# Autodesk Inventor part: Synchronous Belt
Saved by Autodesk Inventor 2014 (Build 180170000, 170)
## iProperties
Created: 2013-12
Part Number: Synchronous Belt
Material: Rubber
Document SubType Name: Modeling
Designer: Bram
Density: 1 g/cm^3
Appearance: Rubber - Black - Version 1.1
CustomPartVersion: 1
Author: Bram
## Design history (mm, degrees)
sketch "Sketch Path"
  geometry: L1 (7.016, -9.44)-(-22.347, -31.263); L2 (-32.146, -26.704)-(-56.472, 373.578); L3 (-34.584, 375.594)-(11.673, 1.443); A1 r 6.145 centre (-26.012, -26.332) between (-32.146, -26.704) and (-22.347, -31.263); A2 r 10.996 centre (-45.496, 374.245) between (-34.584, 375.594) and (-56.472, 373.578)
  constraints: 6 end point, 4 point on circle, 2 centre point, 3 other
node "Cross Section Plane"
workaxis "Work Axis1"
workaxis "Work Axis2"
workaxis "Work Axis3"
workplane "Work Plane2"
workplane "Work Plane3"
workplane "Work Plane4"
workpoint "Work Point1"
sketch "Sketch3"
  geometry: L1 (0.664, 0)-(-0.664, 0); L2 (-0.664, 0)-(-0.387, 0.762); L3 (-0.387, 0.762)-(0.387, 0.762); L4 (0.387, 0.762)-(0.664, 0); L5 (0, 0)-(0, 0.762); L6 (-0.572, 0.254)-(0.572, 0.254)
  constraints: 13 end point, 3 parallel, 2 midpoint, 2 perpendicular, 2 point on line, 1 horizontal alignment, 1 vertical, 1 other
feature "iSBeltToothT:1" sketch "Sketch3"
sketch "Cross Section"
  geometry: L1 (-3.175, 0.381)-(3.175, 0.381); L2 (3.175, 0.381)-(3.175, -0.254); L3 (3.175, -0.254)-(-3.175, -0.254); L4 (-3.175, -0.254)-(-3.175, 0.381); L5 (-3.175, 0)-(3.175, 0); 2 further points
  constraints: 10 end point, 2 parallel, 2 point on line, 1 coincident, 1 horizontal, 1 midpoint, 1 perpendicular, 1 other
  dimensions: "d0" = 6.35 distance between parallel lines of L2 L4 (= da_B); "d4" = 0.254 distance between parallel lines of L3 L5 (= da_a); "d5" = 0.381 distance between parallel lines of L5 L1 (= da_a2)
feature "Belt" sketch "Cross Section" dims "d2" = 0
fillet "Fillet1" dims "d21" = 0.127 (= d13)
body "Solid1"
pattern_linear "Rectangular Pattern1" dims "d20" = 2.032 (= da_pb)
other parameters: "da_B" = 6.35 [user parameter; used in 2 equation terms], "da_pb" = 2.032 [user parameter; used in 1 equation term], "da_L" = 874.07465 [user parameter], "da_a" = 0.254 [user parameter; used in 2 equation terms], "da_S" = 1.143 [user parameter; used in 1 equation term], "da_Beta" = 20 deg [user parameter; used in 1 equation term], "da_Ht" = 0.508 [user parameter; used in 1 equation term], "da_H" = 1.143 [user parameter], "da_a2" = 0.381 [user parameter; used in 1 equation term], "d6" = 0, "d7" = 0, "d8" = 0, "d9" = 0, "d10" = 0, "d11" = 0, "d12" = 0.127, "d13" = 0.127
